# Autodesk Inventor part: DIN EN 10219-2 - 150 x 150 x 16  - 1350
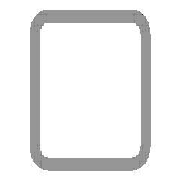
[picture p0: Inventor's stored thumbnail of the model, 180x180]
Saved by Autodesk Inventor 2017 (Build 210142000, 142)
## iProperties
_CCFamilyMember: 76
_CCFamilyDisplayName: DIN EN 10219-2 (Square Hollow Section - Cold Formed) - Cold formed welded structural hollow sections of non-alloy and fine grain structural steel
_FrameMemberDoc: Frame Member File
_Version: 15.0.0
_GetPNFromCC: 1
Created: 2017-11
Part Number: DIN EN 10219-2 - 150 x 150 x 16  - 1350
Material: Steel, Mild
Description: Cold formed welded structural hollow sections of non-alloy and fine grain structural steel
Document SubType Name: Modeling
Standard: DIN
Designer: iusti
Standard Revision: 2006-07
Standards Organization: DIN
Language: en-US
Size Designation: 150 x 150 x 16
Categories: <MemberInstance><Categories><Category DisplayName="Structural Shapes" InternalName="089c4875-fa83-4c05-b084-43b9cc11f5ed" Mnemonic="GRDR"><CategoryParameter Dis
Stock Number: 150 x 150 x 16
Mass: 79240 g
Surface Area: 12767.4 cm^2
Volume: 10094.3 cm^3
Density: 7.85 g/cm^3
Appearance: Semi-Polished
IsCustomPart: 1
G_L: 1350.000 mm
G_W: 150.000 mm
G_H: 150.000 mm
+E3F72FB6-EDBE-4075-8A55-21F95EDF68B6+CUTDETAIL1: Cut
+0D64326D-6ACF-4319-9054-E2A081320EBA+CUTDETAIL2: Cut
Author: iusti
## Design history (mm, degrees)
node "Start plane"
node "End plane"
sketch "Sketch"
  geometry: L1 (-75, -27)-(-75, 27); L2 (-27, 75)-(27, 75); L3 (75, 27)-(75, -27); L4 (27, -75)-(-27, -75); L5 (-27, 59)-(27, 59); L6 (59, 27)-(59, -27); L7 (27, -59)-(-27, -59); L8 (-59, -27)-(-59, 27); L9 (0, 118.918)-(0, -118.918) reference; L10 (-118.918, 0)-(118.918, 0) reference; A1 r 48 centre (-27, -27) between (-75, -27) and (-27, -75); A2 r 48 centre (-27, 27) between (-27, 75) and (-75, 27); A3 r 48 centre (27, 27) between (75, 27) and (27, 75); A4 r 48 centre (27, -27) between (27, -75) and (75, -27); A5 r 32 centre (-27, 27) between (-27, 59) and (-59, 27); A6 r 32 centre (27, 27) between (59, 27) and (27, 59); A7 r 32 centre (27, -27) between (27, -59) and (59, -27); A8 r 32 centre (-27, -27) between (-59, -27) and (-27, -59)
  constraints: 16 end point, 16 point on circle, 8 centre point, 8 tangent, 4 parallel, 3 equal radius, 2 perpendicular, 7 other
  dimensions: "d7" = 48 radius of A1 (= G_IR); "d10" = 150 distance between parallel lines of L2 L4 (= G_H); "d11" = 150 distance between parallel lines of L1 L3 (= G_W); "d12" = 16 distance between parallel lines of L3 L6 (= G_T); "d15" = 75 distance between parallel lines of L2 L10 (= 0.5 x d10); "d16" = 75 distance between parallel lines of L9 L3 (= 0.5 x d11)
extrude "Body" new body sketch "Sketch" stored distance "d3" = 1350 (= G_L); taper "d4" = 0 deg
node "Driven Length"
  sketch "Sketch3"
    geometry: L1 (0, 0)-(10, 0) reference
    constraints: 2 end point, 1 horizontal
  workplane "Work Plane3"
  sketch "Sketch4"
    geometry: L1 (-2, 75)-(12, 75) reference; L2 (-2, 1425)-(12, 1425) reference
    dimensions: "d18" = 1350 distance between parallel lines of L1 L2 (derived)
workplane "Work Plane4"
split "Split1"
workplane "Work Plane5"
split "Split2"
body "Solid1"
other parameters: "G_W" = 150 [user parameter; used in 1 equation term], "G_H" = 150 [user parameter; used in 1 equation term], "G_T" = 16 [user parameter; used in 1 equation term], "G_IR" = 48 [user parameter; used in 1 equation term], "G_L" = 1350 (= d18) [user parameter; used in 1 equation term], "G_OFFSET_START" = -75 [user parameter; used in 1 equation term], "G_OFFSET_END" = -75 [user parameter; used in 1 equation term], "d13" = 75 (= -G_OFFSET_START), "d14" = 1425 (= G_OFFSET_END + B_L), "d17" = 90 deg
